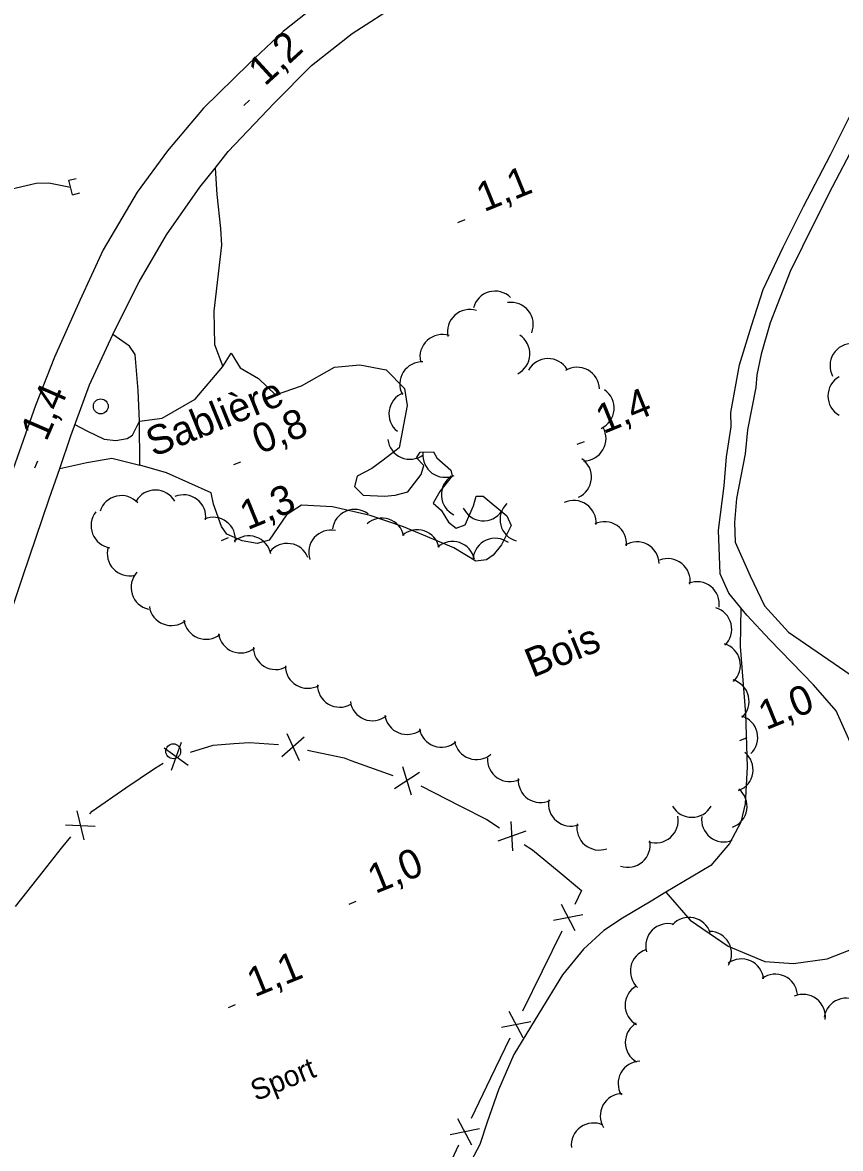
# Model space of a CAD drawing. Extents: x 362852 to 366875, y 5563573 to 5566479.
# Drawn here: x 363257.7 to 363367.7, y 5564877.4 to 5565029 of the extents above; entities that cross this region are included whole.
import ezdxf

# ---------------------------------------------------------------- set-up
doc = ezdxf.new("R2010")
doc.units = 0
for name, color, linetype in [('Niveau 19', 7, 'Continuous'), ('Niveau 21', 7, 'Continuous'), ('Niveau 22', 7, 'Continuous'), ('Niveau 26', 7, 'Continuous'), ('Niveau 3', 7, 'Continuous'), ('Niveau 36', 7, 'Continuous'), ('Niveau 37', 7, 'Continuous'), ('Niveau 4', 7, 'Continuous'), ('Niveau 44', 7, 'Continuous'), ('Niveau 54', 7, 'Continuous'), ('Niveau 56', 7, 'Continuous')]:
    doc.layers.add(name, color=color, linetype=linetype)

msp = doc.modelspace()

# ---------------------------------------------------------------- linework, layer by layer
at = {"layer": 'Niveau 19'}
for points in [[(363370.32, 5564929.11), (363367.09, 5564936.35), (363364.04, 5564939.81), (363358.16, 5564945.88), (363355.07, 5564949.22), (363354.27, 5564950.18), (363352.64, 5564952.15), (363351.49, 5564954.75), (363351.25, 5564960.63), (363352.02, 5564966.63), (363352.37, 5564970.5), (363352.99, 5564974.54), (363352.95, 5564976.5), (363354.1, 5564982.88), (363355.72, 5564988.13), (363357.27, 5564993.02), (363359.99, 5564998.72), (363362.71, 5565004.2), (363366.35, 5565011.16), (363369.45, 5565017.35)], [(363369.96, 5565013.29), (363366.05, 5565005.88), (363362.55, 5564998.83), (363360.92, 5564995.47), (363358.22, 5564988.53), (363357, 5564984.34), (363356.44, 5564981.57), (363356.31, 5564979.86), (363355.17, 5564974.13), (363354.88, 5564970.93), (363353.69, 5564964.89), (363353.44, 5564961.68), (363353.51, 5564959.04), (363355.51, 5564954.52), (363357.47, 5564950.44), (363360.67, 5564946.93), (363369.85, 5564940.62)], [(363283.56, 5565009.38), (363283.78, 5565005.8), (363284.26, 5565001.23), (363284.4, 5564999.01), (363283.37, 5564990.11), (363283.49, 5564985.64), (363284.59, 5564982.67)], [(363264.71, 5564974.88), (363266.3, 5564974.01), (363268.62, 5564972.88), (363270.22, 5564972.72), (363271.72, 5564972.99), (363272.43, 5564973.41), (363273.38, 5564975.31), (363273.21, 5564979.45), (363272.79, 5564984.3), (363272.05, 5564985.39), (363269.8, 5564986.99)], [(363262.65, 5564968.94), (363266.31, 5564969.76), (363269.68, 5564970.33), (363273.43, 5564969.37)]]:
    msp.add_lwpolyline(points, dxfattribs=at)
at = {"layer": 'Niveau 21'}
for points in [[(363372.18, 5565057.69), (363361.37, 5565056.86), (363353.03, 5565055.6), (363345.44, 5565053.87), (363341.3, 5565052.93), (363331.73, 5565049.73), (363323.1, 5565046.35), (363314.99, 5565042.43), (363306.2, 5565037.55), (363298.33, 5565032.24), (363292.69, 5565027.74), (363288.13, 5565023.46), (363282, 5565017.44), (363277.14, 5565011.7), (363273.09, 5565006.11), (363268.51, 5564998.35), (363265.37, 5564991.56), (363261.94, 5564983.91), (363259.38, 5564977.44), (363256.38, 5564968.91), (363254.34, 5564962.36), (363252.17, 5564955.43), (363249.85, 5564948.72)], [(363235.23, 5564889.57), (363237.33, 5564894.18), (363240.03, 5564902.09), (363243.59, 5564912.52), (363245.79, 5564918.73), (363248.83, 5564927.56), (363251.95, 5564937.15), (363254.89, 5564945.97), (363257.71, 5564954.41), (363261.25, 5564964.85), (363262.65, 5564968.94), (363264.15, 5564973.34), (363266.65, 5564980.22), (363269.8, 5564986.99), (363272.24, 5564991.85), (363273.35, 5564994.06), (363277, 5565000.38), (363281.52, 5565006.79), (363283.56, 5565009.38), (363285.33, 5565011.62), (363291.51, 5565018.1), (363296.54, 5565023.16), (363302, 5565027.46), (363308.39, 5565031.6)]]:
    msp.add_lwpolyline(points, dxfattribs=at)
at = {"layer": 'Niveau 22'}
for points in [[(363354.27, 5564950.18), (363354.18, 5564944.99), (363354.9, 5564935.95), (363355.12, 5564928.79), (363354.86, 5564923.81), (363354.29, 5564921.35), (363352.73, 5564918.5), (363350.24, 5564915.54), (363344.17, 5564911.93), (363342.21, 5564910.7), (363338.37, 5564908.42), (363335.83, 5564906.76), (363333.13, 5564904.28), (363330.29, 5564900.8), (363327.1, 5564895.6), (363323.75, 5564890.08), (363321.67, 5564885.32), (363320.17, 5564880.99), (363319.16, 5564877.99), (363315.45, 5564870.94), (363312.89, 5564865.66), (363310, 5564862.69), (363307.83, 5564861.28), (363305.43, 5564860.15)], [(363344.17, 5564911.93), (363347.44, 5564908.16), (363352.55, 5564904.65), (363357.5, 5564902.59), (363361.37, 5564902.33), (363365.91, 5564902.95), (363368.97, 5564904.17), (363372.16, 5564905.28)]]:
    msp.add_lwpolyline(points, dxfattribs=at)
at = {"layer": 'Niveau 26'}
for p, q in [((363263.87, 5565007.75), (363264.85, 5565007.99)), ((363264.38, 5565005.78), (363263.87, 5565007.75)), ((363264.38, 5565005.78), (363265.34, 5565006.04))]:
    msp.add_line(p, q, dxfattribs=at)
at = {"layer": 'Niveau 3'}
for p, q in [((363287.43, 5565017.8), (363288.19, 5565018.5)), ((363316.22, 5565002.06), (363317.18, 5565002.45)), ((363332.28, 5564972.2), (363333.24, 5564972.59)), ((363259.31, 5564969.02), (363259.72, 5564969.98)), ((363286.06, 5564969.47), (363287.02, 5564969.86)), ((363284.4, 5564959.26), (363285.36, 5564959.65)), ((363354.16, 5564932.34), (363355.12, 5564932.73)), ((363301.59, 5564910.31), (363302.55, 5564910.7)), ((363285.36, 5564896.4), (363286.32, 5564896.79))]:
    msp.add_line(p, q, dxfattribs=at)
at = {"layer": 'Niveau 36'}
for centre in [(363268.18, 5564977.3), (363277.92, 5564930.89)]:
    msp.add_circle(centre, 1, dxfattribs=at)
at = {"layer": 'Niveau 37'}
for p, q in [((363295.55, 5564932.77), (363292.54, 5564930.14)), ((363293.2, 5564933.27), (363294.88, 5564929.64)), ((363276.71, 5564931.35), (363279.95, 5564929.01)), ((363279, 5564932.07), (363277.66, 5564928.3)), ((363301.83, 5564929.66), (363307.48, 5564927.63)), ((363311.03, 5564928.05), (363307.68, 5564925.85)), ((363308.77, 5564928.86), (363309.94, 5564925.04)), ((363311.22, 5564926.23), (363316.57, 5564923.51)), ((363264.97, 5564922.86), (363265.91, 5564918.97)), ((363263.45, 5564921.01), (363267.44, 5564920.82)), ((363323.34, 5564921.46), (363323.56, 5564917.47)), ((363325.34, 5564920.13), (363321.57, 5564918.8)), ((363256.71, 5564909.98), (363260.42, 5564914.69)), ((363331.97, 5564906.71), (363330.14, 5564910.27)), ((363333.02, 5564908.87), (363329.09, 5564908.12)), ((363330.18, 5564906.69), (363327.55, 5564901.3)), ((363327.55, 5564901.3), (363324.92, 5564895.9)), ((363324.98, 5564892.33), (363323.13, 5564895.88)), ((363326.01, 5564894.5), (363322.09, 5564893.72)), ((363323.19, 5564892.3), (363320.6, 5564886.89)), ((363320.6, 5564886.89), (363318.01, 5564881.47)), ((363318.09, 5564877.9), (363316.22, 5564881.44)), ((363319.11, 5564880.08), (363315.19, 5564879.27)), ((363316.3, 5564877.86), (363313.75, 5564872.43))]:
    msp.add_line(p, q, dxfattribs=at)
for points in [[(363280.24, 5564930.78), (363283.28, 5564931.73), (363286.09, 5564931.92)], [(363286.09, 5564931.92), (363288.19, 5564932.06), (363292.08, 5564931.78)], [(363296, 5564931.04), (363300.9, 5564930), (363301.83, 5564929.66)], [(363271.57, 5564925.96), (363275.41, 5564928.59), (363276.56, 5564929.29)], [(363266.72, 5564922.46), (363267.03, 5564922.84), (363271.57, 5564925.96)], [(363316.57, 5564923.51), (363320.1, 5564921.71), (363321.8, 5564920.58)], [(363260.42, 5564914.69), (363262.91, 5564917.85), (363264.17, 5564919.38)], [(363325.12, 5564918.36), (363326.24, 5564917.61), (363329.84, 5564914.65)], [(363329.84, 5564914.65), (363332.85, 5564912.17), (363331.93, 5564910.29)]]:
    msp.add_lwpolyline(points, dxfattribs=at)
at = {"layer": 'Niveau 4'}
msp.add_lwpolyline([(363264.12, 5565006.75), (363261.21, 5565007.33), (363259.5, 5565007.29), (363255.43, 5565006.37), (363252.7, 5565005.38), (363249.06, 5565004.48), (363246.86, 5565003.43), (363245.01, 5565002.46), (363243.72, 5565002.24), (363242.95, 5565002.29), (363241.93, 5565003.06), (363240.85, 5565003.59)], dxfattribs=at)
at = {"layer": 'Niveau 44'}
for centre, start, end in [((363321.22, 5564989.81), 45.7946, 165.7726), ((363317.81, 5564987.34), 72.3104, 192.2884), ((363323.36, 5564988.3), 338.628, 98.6059), ((363314.11, 5564983.97), 72.3104, 192.2884), ((363322.9, 5564984.36), 297.2095, 57.1874), ((363369.27, 5564982.77), 88.2822, 208.2601), ((363311.4, 5564980.3), 87.6952, 207.6731), ((363328.34, 5564980.74), 30.9412, 150.9191), ((363332.26, 5564979.56), 1.7306, 121.7086), ((363368.99, 5564978.7), 120.0213, 239.9993), ((363334.23, 5564977.07), 294.858, 54.836), ((363309.93, 5564976.3), 111.7148, 231.6928), ((363333.14, 5564972.97), 269.8124, 29.7904), ((363309.77, 5564973.18), 186.4544, 306.4324), ((363314.49, 5564970.76), 174.1424, 294.1203), ((363331.18, 5564967.79), 295.0398, 55.0178), ((363316.99, 5564965.42), 124.107, 244.0849), ((363275.52, 5564963.04), 29.6655, 149.6434), ((363270.94, 5564962.29), 42.6137, 162.5916), ((363279.31, 5564962.4), 352.8684, 112.8464), ((363331.81, 5564961.64), 355.2956, 115.2735), ((363269.87, 5564961.24), 141.3393, 261.3172), ((363302.33, 5564960.44), 52.8423, 172.8203), ((363319.65, 5564964.9), 205.2418, 325.2198), ((363324.88, 5564962.08), 134.4175, 254.3954), ((363283.29, 5564959.38), 352.8684, 112.8464), ((363306, 5564959.26), 11.717, 131.6949), ((363335.92, 5564958.79), 355.2956, 115.2735), ((363288.1, 5564956.88), 11.3982, 131.3762), ((363299.14, 5564957.65), 78.5027, 198.4807), ((363310.75, 5564957.69), 11.717, 131.6949), ((363272.05, 5564957.49), 163.4928, 283.4708), ((363293.25, 5564955.86), 21.4396, 141.4176), ((363315.5, 5564956.12), 11.717, 131.6949), ((363321.23, 5564956.55), 53.5393, 173.5172), ((363340.3, 5564956.07), 1.7317, 121.7096), ((363344.46, 5564953.81), 351.691, 111.6689), ((363275.25, 5564952.94), 137.2995, 257.2774), ((363348.38, 5564950.71), 351.691, 111.6689), ((363277.68, 5564950.81), 188.3945, 308.3725), ((363350.05, 5564947.33), 313.5135, 73.4914), ((363282.33, 5564948.96), 188.3945, 308.3725), ((363286.98, 5564947.12), 188.3945, 308.3725), ((363291.7, 5564944.89), 179.5604, 299.5384), ((363351.22, 5564942.47), 313.5135, 73.4914), ((363296.01, 5564942.36), 179.5604, 299.5384), ((363352.39, 5564937.61), 313.5135, 73.4914), ((363300.32, 5564939.82), 179.5604, 299.5384), ((363304.72, 5564938), 188.2008, 308.1788), ((363309.37, 5564936.15), 188.2008, 308.1788), ((363353.55, 5564932.75), 313.5135, 73.4914), ((363314, 5564934.44), 190.5549, 310.5329), ((363318.71, 5564932.77), 190.5549, 310.5329), ((363323.2, 5564929.8), 175.8345, 295.8124), ((363352.92, 5564928.41), 290.6984, 50.6764), ((363327.33, 5564926.99), 175.8345, 295.8124), ((363352.11, 5564923.48), 290.6984, 50.6764), ((363331.4, 5564923.82), 169.8641, 289.842), ((363347.69, 5564925), 210.0213, 329.9993), ((363342.85, 5564921.56), 251.0977, 11.0757), ((363352, 5564921.69), 171.8506, 291.8285), ((363335.22, 5564920.6), 169.8641, 289.842), ((363339.08, 5564918.27), 251.0977, 11.0757), ((363347.3, 5564905.53), 17.7944, 137.7724), ((363344.49, 5564904.7), 75.4725, 195.4504), ((363350.04, 5564903.65), 329.2092, 89.1872), ((363342.41, 5564901.31), 107.8557, 227.8337), ((363354.35, 5564899.94), 6.0478, 126.0257), ((363358.9, 5564897.89), 5.5662, 125.5442), ((363341.71, 5564896.71), 120.3131, 240.291), ((363362.65, 5564895.17), 353.2016, 113.1795), ((363368.46, 5564894.67), 51.6229, 171.6009), ((363341.73, 5564891.71), 120.3131, 240.291), ((363340.77, 5564886.19), 91.2165, 211.1944), ((363338.36, 5564881.81), 91.2165, 211.1944), ((363334.47, 5564877.86), 65.6999, 185.6778)]:
    msp.add_arc(centre, 3, start, end, dxfattribs=at)
at = {"layer": 'Niveau 54'}
msp.add_lwpolyline([(363276.45, 5564975.71), (363280.87, 5564978.27), (363284.59, 5564982.67), (363285.71, 5564984.45), (363286.92, 5564982.5), (363289.41, 5564981.07), (363291.7, 5564978.86), (363295.2, 5564980.08), (363299.62, 5564982.56), (363303.03, 5564982.89), (363306.58, 5564982.24), (363309.05, 5564979.72), (363309.39, 5564977.42), (363308.33, 5564971.72), (363306.15, 5564970.05), (363304.63, 5564968.95), (363302.66, 5564967.9), (363302.3, 5564966.5), (363303.46, 5564965.37), (363306.35, 5564965.2), (363307.79, 5564965.36), (363309.48, 5564965.82), (363311.27, 5564968.14), (363311.63, 5564969.36), (363310.65, 5564970.38), (363311.15, 5564971.14), (363312.94, 5564971.2), (363313.4, 5564970.4), (363315.27, 5564968.71), (363315.46, 5564967.97), (363313.78, 5564965.83), (363312.88, 5564964.3), (363313.98, 5564963.32), (363314.96, 5564961.72), (363316, 5564960.9), (363317.19, 5564961.34), (363318.3, 5564963.94), (363318.67, 5564965.24), (363319.63, 5564965.2), (363322.8, 5564962.58), (363323.38, 5564961.28), (363322.09, 5564958.66), (363320.95, 5564957.27), (363320.08, 5564956.65), (363318.62, 5564956.46), (363315.68, 5564958.25), (363308.92, 5564961.1), (363304.4, 5564962.6), (363299.33, 5564963.78), (363295.19, 5564964.02), (363293.15, 5564962.69), (363290.85, 5564959.3), (363289.21, 5564958.86), (363287.19, 5564959.2), (363285.12, 5564960.09), (363284.43, 5564961.12), (363283.35, 5564964.13), (363283.03, 5564965.68), (363277.04, 5564968.35), (363273.43, 5564969.37), (363273.38, 5564975.31), (363276.45, 5564975.71)], dxfattribs=at)

# ---------------------------------------------------------------- texts
at = {"layer": 'Niveau 3'}
for s, rotation, p in [('1,2  ', 42.439, (363290.25, 5565020.3)), ('1,1  ', 22.09, (363319.73, 5565003.42)), ('1,4  ', 66.5945, (363260.86, 5564972.46)), ('1,4  ', 22.09, (363335.79, 5564973.56)), ('0,8  ', 22.09, (363289.57, 5564970.83)), ('1,3  ', 22.09, (363287.91, 5564960.62)), ('1,0  ', 22.09, (363357.67, 5564933.7)), ('1,0  ', 22.09, (363305.1, 5564911.67)), ('1,1  ', 22.09, (363288.87, 5564897.76))]:
    msp.add_text(s, height=3.93, rotation=rotation, dxfattribs=at).set_placement(p)
at = {"layer": 'Niveau 44'}
msp.add_text('Bois', height=3.93, rotation=22.09, dxfattribs=at).set_placement((363326.25, 5564940.74))
at = {"layer": 'Niveau 54'}
msp.add_text('Sablière', height=3.93, rotation=22.09, dxfattribs=at).set_placement((363275.27, 5564970.45))
at = {"layer": 'Niveau 56'}
msp.add_text('Sport', height=2.81, rotation=22.09, dxfattribs=at).set_placement((363289.04, 5564883.78))

doc.saveas('drawing.dxf')
